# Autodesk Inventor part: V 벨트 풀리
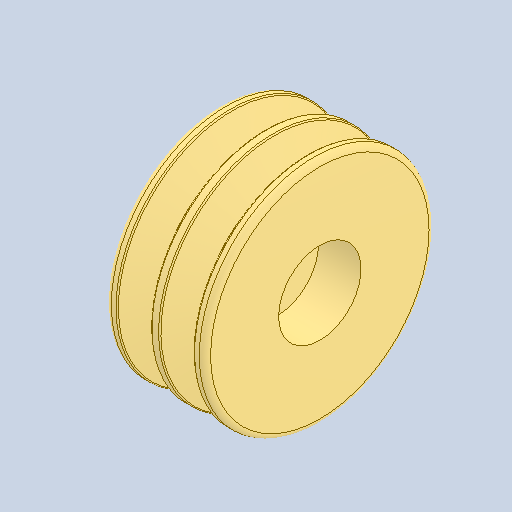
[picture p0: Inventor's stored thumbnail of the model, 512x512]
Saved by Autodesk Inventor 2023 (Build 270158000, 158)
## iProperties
Created: 2024-09
Part Number: V 벨트 풀리
Material: 강철, 주조
Document SubType Name: Modeling
Designer: home
Density: 7.85 g/cm^3
Appearance: 기본값
Author: jhkim
Sending System: Autodesk Inventor 2025
Preprocessor: ST-DEVELOPER v20
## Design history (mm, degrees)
feature "솔리드1"
node "솔리드2"
